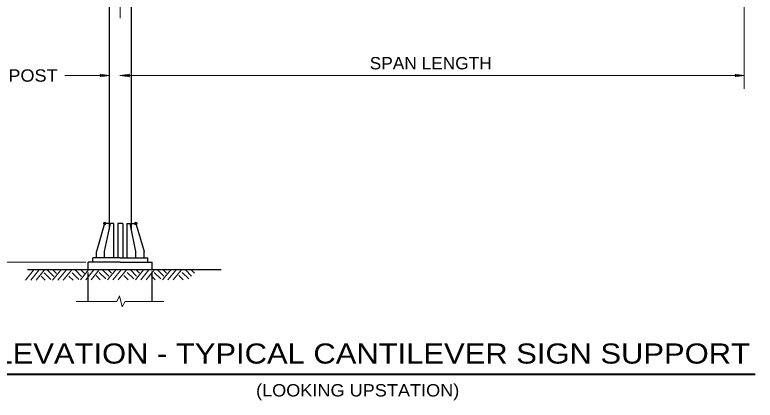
# Model space of a CAD drawing. Extents: x 312601.858 to 312602.699, y 144420.109 to 144420.704.
# Drawn here: x 312601.9725 to 312602.1529, y 144420.4552 to 144420.549 of the extents above; entities that cross this region are included whole.
import ezdxf
from ezdxf.enums import TextEntityAlignment as Align

# ---------------------------------------------------------------- set-up
doc = ezdxf.new("R2010")
doc.units = 0
doc.header["$LTSCALE"] = 0.0012
doc.header["$PDMODE"] = 32
doc.header["$PDSIZE"] = 0.0006
doc.linetypes.add('DOT_DASHED', pattern=[7.7, 5, -1.2, 0.3, -1.2])
doc.linetypes.add('MEDIUM_DASHED', pattern=[4.5, 3, -1.5])
doc.layers.add('1', color=7, linetype='Continuous', lineweight=13)
doc.layers.add('2', color=7, linetype='Continuous', lineweight=25)

msp = doc.modelspace()

# ---------------------------------------------------------------- linework, layer by layer
at = {"layer": '1', "linetype": 'DOT_DASHED'}
msp.add_line((312601.9982, 144420.6482), (312601.9982, 144420.4826), dxfattribs=at)
at = {"layer": '1', "lineweight": 25}
for p, q in [((312601.9955, 144420.5836), (312601.9955, 144420.4967)), ((312602.0009, 144420.5836), (312602.0009, 144420.4967)), ((312601.9944, 144420.4982), (312601.9924, 144420.4914)), ((312601.9955, 144420.4982), (312601.9944, 144420.4982)), ((312601.9966, 144420.4982), (312601.9958, 144420.4982)), ((312601.9966, 144420.4982), (312601.9966, 144420.4898)), ((312601.9976, 144420.4982), (312601.9976, 144420.4898)), ((312601.9988, 144420.4982), (312601.9976, 144420.4982)), ((312601.9988, 144420.4982), (312601.9988, 144420.4898)), ((312601.9998, 144420.4982), (312601.9998, 144420.4898)), ((312601.9998, 144420.4982), (312602.0006, 144420.4982)), ((312602.0009, 144420.4982), (312602.002, 144420.4982)), ((312602.002, 144420.4982), (312602.004, 144420.4914)), ((312601.9924, 144420.4898), (312601.9924, 144420.4914)), ((312601.9944, 144420.4898), (312601.9944, 144420.4914)), ((312602.002, 144420.4898), (312602.002, 144420.4914)), ((312602.004, 144420.4898), (312602.004, 144420.4914)), ((312601.9915, 144420.4888), (312601.9915, 144420.4898)), ((312601.9982, 144420.4898), (312601.9915, 144420.4898)), ((312601.9982, 144420.4898), (312602.0049, 144420.4898)), ((312602.0049, 144420.4888), (312602.0049, 144420.4898)), ((312601.9982, 144420.4888), (312601.9904, 144420.4888)), ((312601.9904, 144420.487), (312601.9904, 144420.4888)), ((312601.9982, 144420.4888), (312602.006, 144420.4888)), ((312602.006, 144420.487), (312602.006, 144420.4888)), ((312601.9756, 144420.487), (312602.0228, 144420.487))]:
    msp.add_line(p, q, dxfattribs=at)
at = {"layer": '1'}
for p, q in [((312602.1502, 144420.5827), (312602.1502, 144420.531)), ((312601.9847, 144420.5342), (312601.9955, 144420.5342)), ((312601.9955, 144420.5342), (312601.9925, 144420.5342)), ((312601.9997, 144420.5342), (312601.9981, 144420.5342)), ((312601.9982, 144420.5342), (312602.1502, 144420.5342)), ((312601.9898, 144420.4888), (312601.9399, 144420.4888)), ((312601.9751, 144420.4844), (312601.9771, 144420.4868)), ((312601.9764, 144420.4844), (312601.9784, 144420.4868)), ((312601.9777, 144420.4844), (312601.9797, 144420.4868)), ((312601.9797, 144420.4862), (312601.9813, 144420.4846)), ((312601.9805, 144420.4868), (312601.982, 144420.4853)), ((312601.9817, 144420.4844), (312601.9837, 144420.4868)), ((312601.9819, 144420.4868), (312601.9827, 144420.486)), ((312601.983, 144420.4844), (312601.985, 144420.4868)), ((312601.9843, 144420.4844), (312601.9863, 144420.4868)), ((312601.9865, 144420.4862), (312601.9881, 144420.4846)), ((312601.9873, 144420.4868), (312601.9888, 144420.4853)), ((312601.9885, 144420.4845), (312601.9905, 144420.4869)), ((312601.9887, 144420.4868), (312601.9895, 144420.486)), ((312601.9898, 144420.4845), (312601.9918, 144420.4869)), ((312601.9911, 144420.4845), (312601.9931, 144420.4869)), ((312601.9931, 144420.4863), (312601.9947, 144420.4847)), ((312601.9939, 144420.4869), (312601.9954, 144420.4854)), ((312601.9951, 144420.4845), (312601.9971, 144420.4869)), ((312601.9953, 144420.4869), (312601.9961, 144420.4861)), ((312601.9964, 144420.4845), (312601.9984, 144420.4869)), ((312601.9977, 144420.4845), (312601.9997, 144420.4869)), ((312601.9999, 144420.4863), (312602.0015, 144420.4847)), ((312602.0007, 144420.4869), (312602.0022, 144420.4854)), ((312602.0019, 144420.4845), (312602.0039, 144420.4869)), ((312602.0021, 144420.4869), (312602.0029, 144420.4861)), ((312602.0032, 144420.4845), (312602.0052, 144420.4869)), ((312602.0045, 144420.4845), (312602.0065, 144420.4869)), ((312602.0065, 144420.4863), (312602.0081, 144420.4847)), ((312602.0073, 144420.4869), (312602.0088, 144420.4854)), ((312602.0085, 144420.4845), (312602.0105, 144420.4869)), ((312602.0087, 144420.4869), (312602.0095, 144420.4861)), ((312602.0098, 144420.4845), (312602.0118, 144420.4869)), ((312602.0111, 144420.4845), (312602.0131, 144420.4869)), ((312602.0133, 144420.4863), (312602.0149, 144420.4847)), ((312602.0141, 144420.4869), (312602.0156, 144420.4854)), ((312602.0155, 144420.4869), (312602.0163, 144420.4861)), ((312601.9789, 144420.4854), (312601.9799, 144420.4844)), ((312601.9857, 144420.4854), (312601.9867, 144420.4844)), ((312601.9923, 144420.4855), (312601.9933, 144420.4845)), ((312601.9991, 144420.4855), (312602.0001, 144420.4845)), ((312602.0057, 144420.4855), (312602.0067, 144420.4845)), ((312602.0125, 144420.4855), (312602.0135, 144420.4845))]:
    msp.add_line(p, q, dxfattribs=at)
at = {"layer": '1', "linetype": 'MEDIUM_DASHED', "lineweight": 25}
for p, q in [((312601.9904, 144420.4792), (312601.9904, 144420.4863)), ((312602.006, 144420.4792), (312602.006, 144420.4865))]:
    msp.add_line(p, q, dxfattribs=at)
at = {"layer": '1'}
for points in [[(312601.9933, 144420.5345), (312601.9955, 144420.5342), (312601.9933, 144420.5339), (312601.9935, 144420.5342)], [(312602.0005, 144420.5339), (312601.9982, 144420.5342), (312602.0005, 144420.5345), (312602.0002, 144420.5342)], [(312602.0005, 144420.5339), (312601.9982, 144420.5342), (312602.0005, 144420.5345), (312602.0002, 144420.5342)], [(312602.0005, 144420.5339), (312601.9982, 144420.5342), (312602.0005, 144420.5345), (312602.0002, 144420.5342)], [(312602.0005, 144420.5339), (312601.9982, 144420.5342), (312602.0005, 144420.5345), (312602.0002, 144420.5342)], [(312602.148, 144420.5345), (312602.1502, 144420.5342), (312602.148, 144420.5339), (312602.1482, 144420.5342)], [(312602.148, 144420.5345), (312602.1502, 144420.5342), (312602.148, 144420.5339), (312602.1482, 144420.5342)]]:
    msp.add_lwpolyline(points, close=True, dxfattribs=at)
for p in [(312601.9944, 144420.4982), (312602.002, 144420.4982)]:
    msp.add_point(p, dxfattribs=at)
at = {"layer": '2'}
for p, q in [((312601.9944, 144420.4914), (312601.9958, 144420.4982)), ((312602.002, 144420.4914), (312602.0006, 144420.4982))]:
    msp.add_line(p, q, dxfattribs=at)
at = {"layer": '2', "lineweight": 13}
for p, q in [((312601.9875, 144420.4792), (312601.9974, 144420.4792)), ((312601.9994, 144420.4792), (312602.0088, 144420.4792))]:
    msp.add_line(p, q, dxfattribs=at)
at = {"layer": '2', "lineweight": 40}
msp.add_line((312601.9617, 144420.4615), (312602.1529, 144420.4615), dxfattribs=at)
at = {"layer": '2', "lineweight": 13}
msp.add_lwpolyline([(312601.9974, 144420.4792), (312601.998, 144420.4806), (312601.9987, 144420.4779), (312601.9994, 144420.4792)], dxfattribs=at)

# ---------------------------------------------------------------- texts
at = {"layer": '2'}
for s, height, width, p in [('SPAN LENGTH', 0.003, 1.05, (312602.07385, 144420.5357)), ('STEEL POST', 0.003, 1.1, (312601.96935, 144420.5327)), ('ELEVATION - TYPICAL CANTILEVER SIGN SUPPORT', 0.0049, 1.15, (312602.0572, 144420.4641)), ('(LOOKING UPSTATION)', 0.003, 1.1, (312602.05605, 144420.4561))]:
    msp.add_text(s, height=height, dxfattribs=dict(at, width=width)).set_placement(p, align=Align.CENTER)

doc.saveas('drawing.dxf')
